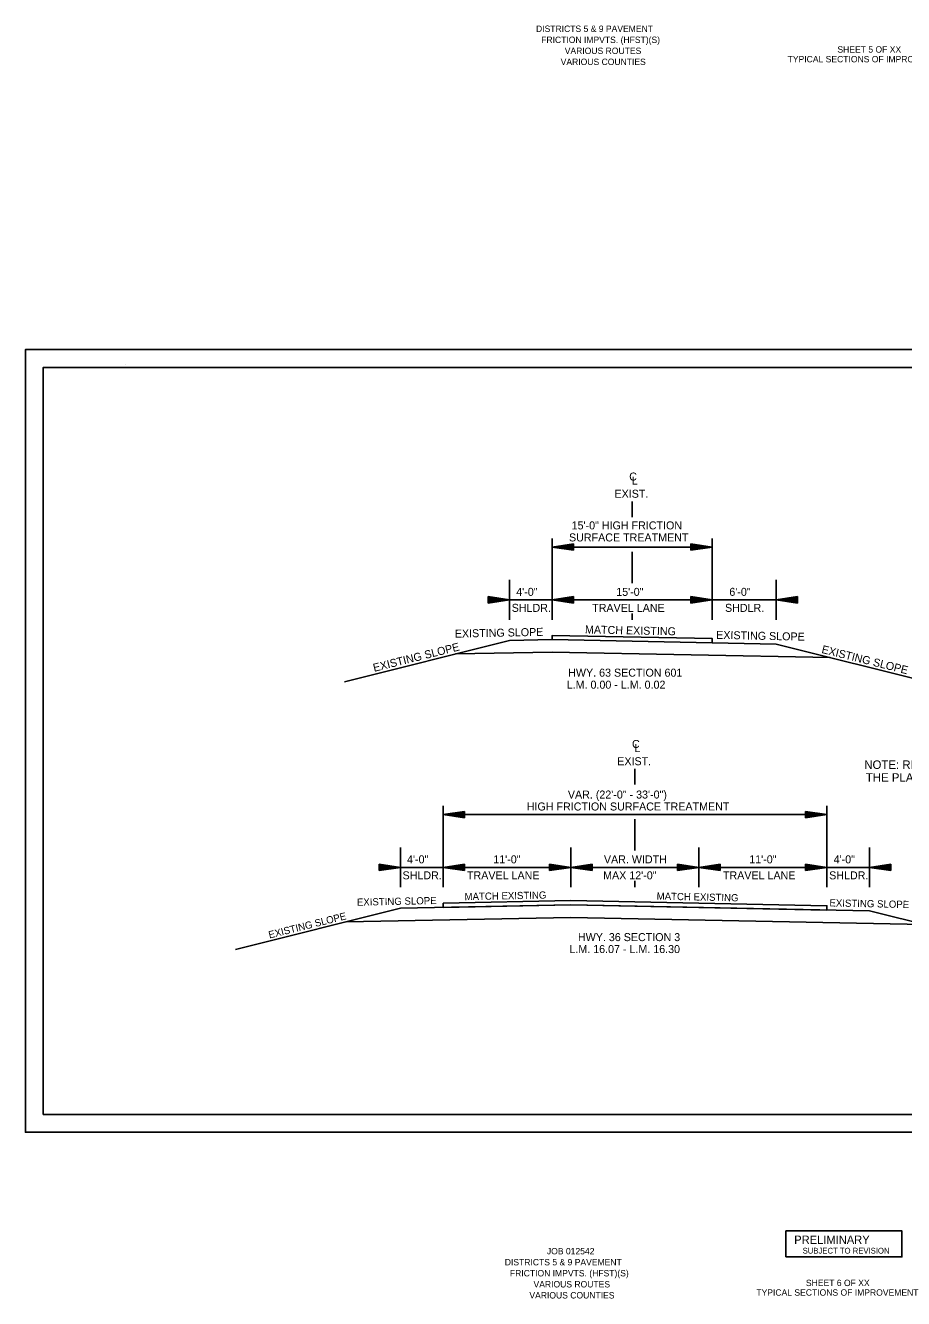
# Model space of a CAD drawing. Extents: x 34757 to 38214, y 51436 to 59430.
# Drawn here: x 34757 to 35992, y 51436 to 53225 of the extents above; entities that cross this region are included whole.
import ezdxf

# ---------------------------------------------------------------- set-up
doc = ezdxf.new("R2010")
doc.units = 0
for name, color, linetype in [('Default', 7, 'Continuous'), ('DSN_DRFT_Junk-No-Plot', 7, 'Continuous'), ('R_Border Notes', 7, 'Continuous'), ('R_Draft', 7, 'Continuous'), ('SHET_Border-Lines', 7, 'Continuous')]:
    doc.layers.add(name, color=color, linetype=linetype)

msp = doc.modelspace()

# ---------------------------------------------------------------- linework, layer by layer
at = {"layer": 'Default'}
for p, q in [((35610, 52534.2), (35610, 52556.2)), ((35497.5, 52389.9), (35497.5, 52504.3)), ((35722.5, 52389.9), (35722.5, 52504.3)), ((35527.5, 52496.6), (35497.5, 52492.1)), ((35722.5, 52492.1), (35497.5, 52492.1)), ((35527.5, 52487.6), (35497.5, 52492.1)), ((35527.5, 52495.9), (35502.5, 52492.1)), ((35527.5, 52488.4), (35502.5, 52492.1)), ((35527.5, 52495.1), (35507.6, 52492.1)), ((35527.5, 52489.1), (35507.6, 52492.1)), ((35527.5, 52494.4), (35512.6, 52492.1)), ((35527.5, 52489.9), (35512.6, 52492.1)), ((35527.5, 52493.6), (35517.7, 52492.1)), ((35527.5, 52490.7), (35517.7, 52492.1)), ((35527.5, 52492.8), (35522.7, 52492.1)), ((35527.5, 52491.4), (35522.7, 52492.1)), ((35527.5, 52487.6), (35527.5, 52496.6)), ((35610, 52441.4), (35610, 52485.3)), ((35692.5, 52496.6), (35722.5, 52492.1)), ((35692.5, 52496.6), (35692.5, 52487.6)), ((35692.5, 52495.9), (35717.5, 52492.1)), ((35692.5, 52495.1), (35712.3, 52492.1)), ((35692.5, 52494.4), (35707.3, 52492.1)), ((35692.5, 52493.6), (35702.2, 52492.1)), ((35692.5, 52492.8), (35697.2, 52492.1)), ((35692.5, 52487.6), (35722.5, 52492.1)), ((35692.5, 52490.7), (35702.2, 52492.1)), ((35692.5, 52489.2), (35712.3, 52492.1)), ((35692.5, 52488.4), (35717.5, 52492.1)), ((35692.5, 52489.9), (35707.3, 52492.1)), ((35692.5, 52491.4), (35697.2, 52492.1)), ((35437.5, 52389.9), (35437.5, 52445.9)), ((35812.5, 52389.9), (35812.5, 52445.9)), ((35407.5, 52422.4), (35437.5, 52417.9)), ((35407.5, 52422.4), (35407.5, 52413.4)), ((35407.5, 52421.6), (35432.5, 52417.9)), ((35407.5, 52420.9), (35427.3, 52417.9)), ((35407.5, 52420.1), (35422.3, 52417.9)), ((35407.5, 52419.3), (35417.2, 52417.9)), ((35407.5, 52418.6), (35412.2, 52417.9)), ((35407.5, 52413.4), (35437.5, 52417.9)), ((35407.5, 52416.4), (35417.2, 52417.9)), ((35407.5, 52414.9), (35427.3, 52417.9)), ((35407.5, 52414.1), (35432.5, 52417.9)), ((35407.5, 52415.6), (35422.3, 52417.9)), ((35407.5, 52417.2), (35412.2, 52417.9)), ((35437.5, 52417.9), (35497.5, 52417.9)), ((35527.5, 52422.4), (35497.5, 52417.9)), ((35497.5, 52417.9), (35722.5, 52417.9)), ((35527.5, 52413.4), (35497.5, 52417.9)), ((35527.5, 52421.6), (35502.5, 52417.9)), ((35527.5, 52414.1), (35502.5, 52417.9)), ((35527.5, 52420.9), (35507.6, 52417.9)), ((35527.5, 52414.9), (35507.6, 52417.9)), ((35527.5, 52420.1), (35512.6, 52417.9)), ((35527.5, 52415.6), (35512.6, 52417.9)), ((35527.5, 52419.3), (35517.7, 52417.9)), ((35527.5, 52416.4), (35517.7, 52417.9)), ((35527.5, 52418.6), (35522.7, 52417.9)), ((35527.5, 52417.2), (35522.7, 52417.9)), ((35527.5, 52413.4), (35527.5, 52422.4)), ((35692.5, 52422.4), (35722.5, 52417.9)), ((35692.5, 52422.4), (35692.5, 52413.4)), ((35692.5, 52421.6), (35717.5, 52417.9)), ((35692.5, 52420.9), (35712.3, 52417.9)), ((35692.5, 52420.1), (35707.3, 52417.9)), ((35692.5, 52419.3), (35702.2, 52417.9)), ((35692.5, 52418.6), (35697.2, 52417.9)), ((35692.5, 52413.4), (35722.5, 52417.9)), ((35692.5, 52416.4), (35702.2, 52417.9)), ((35692.5, 52414.9), (35712.3, 52417.9)), ((35692.5, 52414.1), (35717.5, 52417.9)), ((35692.5, 52415.6), (35707.3, 52417.9)), ((35692.5, 52417.2), (35697.2, 52417.9)), ((35812.5, 52417.9), (35722.5, 52417.9)), ((35842.5, 52422.4), (35812.5, 52417.9)), ((35842.5, 52413.4), (35812.5, 52417.9)), ((35842.5, 52421.6), (35817.5, 52417.9)), ((35842.5, 52414.1), (35817.5, 52417.9)), ((35842.5, 52420.9), (35822.6, 52417.9)), ((35842.5, 52414.9), (35822.6, 52417.9)), ((35842.5, 52420.1), (35827.6, 52417.9)), ((35842.5, 52415.6), (35827.6, 52417.9)), ((35842.5, 52419.3), (35832.7, 52417.9)), ((35842.5, 52416.4), (35832.7, 52417.9)), ((35842.5, 52418.6), (35837.7, 52417.9)), ((35842.5, 52417.2), (35837.7, 52417.9)), ((35842.5, 52413.4), (35842.5, 52422.4)), ((35610, 52389.9), (35610, 52398.6)), ((35437.5, 52360.8), (35205.5, 52302.8)), ((35497.5, 52368), (35722.5, 52363.5)), ((35497.5, 52362), (35812.5, 52355.7)), ((35722.5, 52363.5), (35722.5, 52357.5)), ((35497.5, 52344.5), (35361.4, 52341.8)), ((35497.5, 52344.5), (35888.6, 52336.7)), ((35812.5, 52355.7), (36044.5, 52297.7)), ((35613.9, 52158.2), (35613.9, 52180.2)), ((35343.9, 52013.9), (35343.9, 52128.3)), ((35883.9, 52013.9), (35883.9, 52128.3)), ((35373.9, 52120.6), (35343.9, 52116.1)), ((35883.9, 52116.1), (35343.9, 52116.1)), ((35373.9, 52111.6), (35343.9, 52116.1)), ((35373.9, 52119.9), (35348.9, 52116.1)), ((35373.9, 52112.4), (35348.9, 52116.1)), ((35373.9, 52119.1), (35354.1, 52116.1)), ((35373.9, 52113.2), (35354.1, 52116.1)), ((35373.9, 52118.4), (35359, 52116.1)), ((35373.9, 52113.9), (35359, 52116.1)), ((35373.9, 52117.6), (35364.1, 52116.1)), ((35373.9, 52114.7), (35364.1, 52116.1)), ((35373.9, 52116.9), (35369.1, 52116.1)), ((35373.9, 52115.4), (35369.1, 52116.1)), ((35373.9, 52111.6), (35373.9, 52120.6)), ((35613.9, 52065.4), (35613.9, 52109.4)), ((35853.9, 52120.6), (35883.9, 52116.1)), ((35853.9, 52120.6), (35853.9, 52111.6)), ((35853.9, 52119.9), (35878.9, 52116.1)), ((35853.9, 52119.1), (35873.7, 52116.1)), ((35853.9, 52118.4), (35868.7, 52116.1)), ((35853.9, 52117.6), (35863.6, 52116.1)), ((35853.9, 52116.9), (35858.6, 52116.1)), ((35853.9, 52111.6), (35883.9, 52116.1)), ((35853.9, 52114.7), (35863.6, 52116.1)), ((35853.9, 52113.2), (35873.7, 52116.1)), ((35853.9, 52112.4), (35878.9, 52116.1)), ((35853.9, 52113.9), (35868.7, 52116.1)), ((35853.9, 52115.4), (35858.6, 52116.1)), ((35283.9, 52013.9), (35283.9, 52069.9)), ((35523.9, 52013.9), (35523.9, 52069.9)), ((35703.9, 52013.9), (35703.9, 52069.9)), ((35943.9, 52013.9), (35943.9, 52069.9)), ((35253.9, 52046.4), (35283.9, 52041.9)), ((35253.9, 52046.4), (35253.9, 52037.4)), ((35253.9, 52045.6), (35278.9, 52041.9)), ((35253.9, 52044.9), (35273.7, 52041.9)), ((35253.9, 52044.1), (35268.7, 52041.9)), ((35253.9, 52043.3), (35263.6, 52041.9)), ((35253.9, 52042.6), (35258.6, 52041.9)), ((35253.9, 52037.4), (35283.9, 52041.9)), ((35253.9, 52040.4), (35263.6, 52041.9)), ((35253.9, 52038.9), (35273.7, 52041.9)), ((35253.9, 52038.1), (35278.9, 52041.9)), ((35253.9, 52039.7), (35268.7, 52041.9)), ((35253.9, 52041.2), (35258.6, 52041.9)), ((35343.9, 52041.9), (35283.9, 52041.9)), ((35373.9, 52046.4), (35343.9, 52041.9)), ((35523.9, 52041.9), (35343.9, 52041.9)), ((35373.9, 52037.4), (35343.9, 52041.9)), ((35373.9, 52045.6), (35348.9, 52041.9)), ((35373.9, 52038.1), (35348.9, 52041.9)), ((35373.9, 52044.9), (35354.1, 52041.9)), ((35373.9, 52038.9), (35354.1, 52041.9)), ((35373.9, 52044.1), (35359, 52041.9)), ((35373.9, 52039.7), (35359, 52041.9)), ((35373.9, 52043.4), (35364.1, 52041.9)), ((35373.9, 52040.4), (35364.1, 52041.9)), ((35373.9, 52042.6), (35369.1, 52041.9)), ((35373.9, 52041.2), (35369.1, 52041.9)), ((35373.9, 52037.4), (35373.9, 52046.4)), ((35493.9, 52046.4), (35523.9, 52041.9)), ((35493.9, 52046.4), (35493.9, 52037.4)), ((35493.9, 52045.6), (35518.9, 52041.9)), ((35493.9, 52044.9), (35513.7, 52041.9)), ((35493.9, 52044.1), (35508.7, 52041.9)), ((35493.9, 52043.3), (35503.6, 52041.9)), ((35493.9, 52042.6), (35498.6, 52041.9)), ((35493.9, 52037.4), (35523.9, 52041.9)), ((35493.9, 52040.4), (35503.6, 52041.9)), ((35493.9, 52038.9), (35513.7, 52041.9)), ((35493.9, 52038.1), (35518.9, 52041.9)), ((35493.9, 52039.7), (35508.7, 52041.9)), ((35493.9, 52041.2), (35498.6, 52041.9)), ((35553.9, 52046.4), (35523.9, 52041.9)), ((35703.9, 52041.9), (35523.9, 52041.9)), ((35553.9, 52037.4), (35523.9, 52041.9)), ((35553.9, 52045.6), (35528.9, 52041.9)), ((35553.9, 52038.1), (35528.9, 52041.9)), ((35553.9, 52044.9), (35534.1, 52041.9)), ((35553.9, 52038.9), (35534.1, 52041.9)), ((35553.9, 52044.1), (35539, 52041.9)), ((35553.9, 52039.7), (35539, 52041.9)), ((35553.9, 52043.4), (35544.1, 52041.9)), ((35553.9, 52040.4), (35544.1, 52041.9)), ((35553.9, 52042.6), (35549.1, 52041.9)), ((35553.9, 52041.2), (35549.1, 52041.9)), ((35553.9, 52037.4), (35553.9, 52046.4)), ((35673.9, 52046.4), (35703.9, 52041.9)), ((35673.9, 52046.4), (35673.9, 52037.4)), ((35673.9, 52045.6), (35698.9, 52041.9)), ((35673.9, 52044.9), (35693.7, 52041.9)), ((35673.9, 52044.1), (35688.7, 52041.9)), ((35673.9, 52043.3), (35683.6, 52041.9)), ((35673.9, 52042.6), (35678.6, 52041.9)), ((35673.9, 52037.4), (35703.9, 52041.9)), ((35673.9, 52040.4), (35683.6, 52041.9)), ((35673.9, 52038.9), (35693.7, 52041.9)), ((35673.9, 52038.1), (35698.9, 52041.9)), ((35673.9, 52039.7), (35688.7, 52041.9)), ((35673.9, 52041.2), (35678.6, 52041.9)), ((35733.9, 52046.4), (35703.9, 52041.9)), ((35883.9, 52041.9), (35703.9, 52041.9)), ((35733.9, 52037.4), (35703.9, 52041.9)), ((35733.9, 52045.6), (35708.9, 52041.9)), ((35733.9, 52038.1), (35708.9, 52041.9)), ((35733.9, 52044.9), (35714.1, 52041.9)), ((35733.9, 52038.9), (35714.1, 52041.9)), ((35733.9, 52044.1), (35719, 52041.9)), ((35733.9, 52039.7), (35719, 52041.9)), ((35733.9, 52043.4), (35724.1, 52041.9)), ((35733.9, 52040.4), (35724.1, 52041.9)), ((35733.9, 52042.6), (35729.1, 52041.9)), ((35733.9, 52041.2), (35729.1, 52041.9)), ((35733.9, 52037.4), (35733.9, 52046.4)), ((35853.9, 52046.4), (35883.9, 52041.9)), ((35853.9, 52046.4), (35853.9, 52037.4)), ((35853.9, 52045.6), (35878.9, 52041.9)), ((35853.9, 52044.9), (35873.7, 52041.9)), ((35853.9, 52044.1), (35868.7, 52041.9)), ((35853.9, 52043.3), (35863.6, 52041.9)), ((35853.9, 52042.6), (35858.6, 52041.9)), ((35853.9, 52037.4), (35883.9, 52041.9)), ((35853.9, 52040.4), (35863.6, 52041.9)), ((35853.9, 52038.9), (35873.7, 52041.9)), ((35853.9, 52038.1), (35878.9, 52041.9)), ((35853.9, 52039.7), (35868.7, 52041.9)), ((35853.9, 52041.2), (35858.6, 52041.9)), ((35943.9, 52041.9), (35883.9, 52041.9)), ((35973.9, 52046.4), (35943.9, 52041.9)), ((35973.9, 52037.4), (35943.9, 52041.9)), ((35973.9, 52045.6), (35948.9, 52041.9)), ((35973.9, 52038.1), (35948.9, 52041.9)), ((35973.9, 52044.9), (35954.1, 52041.9)), ((35973.9, 52038.9), (35954.1, 52041.9)), ((35973.9, 52044.1), (35959, 52041.9)), ((35973.9, 52039.7), (35959, 52041.9)), ((35973.9, 52043.4), (35964.1, 52041.9)), ((35973.9, 52040.4), (35964.1, 52041.9)), ((35973.9, 52042.6), (35969.1, 52041.9)), ((35973.9, 52041.2), (35969.1, 52041.9)), ((35973.9, 52037.4), (35973.9, 52046.4)), ((35613.9, 52013.9), (35613.9, 52022.7)), ((35283.9, 51984.3), (35051.9, 51926.4)), ((35523.9, 51989.2), (35283.9, 51984.3)), ((35523.9, 51995.2), (35343.9, 51991.6)), ((35343.9, 51991.6), (35343.9, 51985.5)), ((35523.9, 51995.2), (35883.9, 51988)), ((35883.9, 51988), (35883.9, 51981.9)), ((35523.9, 51971.6), (35207.8, 51965.3)), ((35523.9, 51971.6), (36020, 51961.7)), ((35943.9, 51980.7), (36175.9, 51922.8))]:
    msp.add_line(p, q, dxfattribs=at)
for points in [[(35497.5, 52362), (35437.5, 52360.8)], [(35523.9, 51989.2), (35943.9, 51980.7)]]:
    msp.add_lwpolyline(points, dxfattribs=at)
for points in [[(35497.5, 52362), (35722.5, 52357.5), (35722.5, 52363.5), (35497.5, 52368)], [(35343.9, 51991.6), (35343.9, 51985.5), (35523.9, 51989.2), (35883.9, 51981.9), (35883.9, 51988), (35523.9, 51995.2)], [(35826.2, 51494.4), (35989.3, 51494.4), (35989.3, 51530.8), (35826.2, 51530.8)]]:
    msp.add_lwpolyline(points, close=True, dxfattribs=at)
at = {"layer": 'DSN_DRFT_Junk-No-Plot'}
msp.add_lwpolyline([(34756.6, 52769.6), (34756.6, 51669.6), (36456.6, 51669.6), (36456.6, 52769.6)], close=True, dxfattribs=at)
at = {"layer": 'SHET_Border-Lines'}
msp.add_line((34897.7, 52748.2), (34897.7, 52748.2), dxfattribs=at)
msp.add_line((34897.7, 52748.2), (34897.7, 52748.2), dxfattribs=at)
for points in [[(34756.6, 51669.6), (36456.6, 51669.6), (36456.6, 52769.6), (34756.6, 52769.6)], [(34781.6, 51694.6), (36431.6, 51694.6), (36431.6, 52744.6), (34781.6, 52744.6)]]:
    msp.add_lwpolyline(points, close=True, dxfattribs=at)

# ---------------------------------------------------------------- texts
at = {"layer": 'Default'}
for s, height, p in [('C', 11.2, (35605.8, 52585.6)), ('L', 11.2, (35609.2, 52579.9)), ('EXIST.', 11.24, (35585.1, 52561.4)), ('15\'-0" HIGH FRICTION', 11.25, (35524.8, 52516.9)), ('SURFACE TREATMENT', 11.25, (35521.1, 52500)), ('4\'-0"', 11.25, (35446.9, 52423.5)), ('15\'-0"', 11.25, (35587.5, 52423.5)), ('6\'-0"', 11.25, (35746.6, 52423.5)), ('SHLDR.', 11.25, (35440.5, 52401)), ('TRAVEL LANE', 11.25, (35553.7, 52401)), ('SHDLR.', 11.25, (35740.5, 52401)), ('HWY. 63 SECTION 601', 11.25, (35520, 52309.9)), ('L.M. 0.00 - L.M. 0.02', 11.25, (35517.9, 52293)), ('C', 11.2, (35609.7, 52209.7)), ('L', 11.2, (35613.1, 52203.9)), ('EXIST.', 11.24, (35589, 52185.4)), ('NOTE: REMOVE PERMANENT PAVEMENT MARKING PRIOR TO ', 12.007, (35936.4, 52180.2)), ('THE PLACEMENT OF HIGH FRICTION SURFACE TREATMENT', 12.007, (35938.6, 52162.2)), ('VAR. (22\'-0" - 33\'-0")', 11.25, (35519.5, 52138.6)), ('HIGH FRICTION SURFACE TREATMENT', 11.25, (35461.7, 52121.8)), ('4\'-0"', 11.25, (35293.3, 52047.5)), ('11\'-0"', 11.25, (35414.6, 52047.5)), ('VAR. WIDTH', 11.25, (35570.2, 52047.5)), ('11\'-0"', 11.25, (35774.6, 52047.5)), ('4\'-0"', 11.25, (35893.3, 52047.5)), ('SHLDR.', 11.25, (35287, 52025)), ('TRAVEL LANE', 11.25, (35377.6, 52025)), ('MAX 12\'-0"', 11.25, (35569.1, 52025)), ('TRAVEL LANE', 11.25, (35737.6, 52025)), ('SHLDR.', 11.25, (35887, 52025)), ('HWY. 36 SECTION 3', 11.25, (35533.7, 51938.2)), ('L.M. 16.07 - L.M. 16.30', 11.25, (35521.7, 51921.4)), ('PRELIMINARY', 11.7, (35837.9, 51512.6)), ('SUBJECT TO REVISION', 8.1, (35849.7, 51499))]:
    msp.add_text(s, height=height, dxfattribs=at).set_placement(p)
for s, height, rotation, p in [('EXISTING SLOPE', 11.25, 1.2244, (35360.6, 52364.7)), ('MATCH EXISTING', 11.25, 358.7756, (35543.5, 52370.7)), ('EXISTING SLOPE', 11.25, 358.7756, (35728, 52363.1)), ('EXISTING SLOPE', 11.25, 14.0368, (35247.1, 52316.7)), ('EXISTING SLOPE', 11.25, 345.9632, (35875.6, 52343.4)), ('MATCH EXISTING', 10.125, 1.146, (35374.3, 51995.7)), ('MATCH EXISTING', 10.125, 358.7756, (35644.3, 51996.5)), ('EXISTING SLOPE', 10.125, 1.2244, (35222.9, 51987.9)), ('EXISTING SLOPE', 10.125, 358.7756, (35887.3, 51987)), ('EXISTING SLOPE', 10.125, 14.0368, (35099.9, 51941.8))]:
    msp.add_text(s, height=height, rotation=rotation, dxfattribs=at).set_placement(p)
at = {"layer": 'R_Border Notes'}
for s, p in [('TYPICAL SECTIONS OF IMPROVEMENT', (35828.6, 53173.4)), ('SHEET 5 OF XX', (35898.6, 53187)), ('TYPICAL SECTIONS OF IMPROVEMENT', (35784.6, 51439.8)), ('SHEET 6 OF XX', (35854.3, 51453.3))]:
    msp.add_text(s, height=9, dxfattribs=at).set_placement(p)
at = {"layer": 'R_Draft'}
for s, p in [('DISTRICTS 5 & 9 PAVEMENT', (35474.7, 53216.1)), ('FRICTION IMPVTS. (HFST)(S)', (35482, 53200.6)), ('VARIOUS ROUTES', (35515.1, 53185.1)), ('VARIOUS COUNTIES', (35509.4, 53169.6)), ('JOB 012542', (35490, 51497.9)), ('DISTRICTS 5 & 9 PAVEMENT', (35430.8, 51482.4)), ('FRICTION IMPVTS. (HFST)(S)', (35438, 51466.9)), ('VARIOUS ROUTES', (35471.2, 51451.4)), ('VARIOUS COUNTIES', (35465.4, 51435.9))]:
    msp.add_text(s, height=9, dxfattribs=at).set_placement(p)

doc.saveas('drawing.dxf')
